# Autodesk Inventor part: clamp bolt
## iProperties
Created: 2006-04
Part Number: clamp bolt
Document SubType Name: Modeling
Designer: E. MOSS
Author: E. MOSS
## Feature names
1. Extrusion1
2. Hole1
3. Hole2
4. Revolution1
